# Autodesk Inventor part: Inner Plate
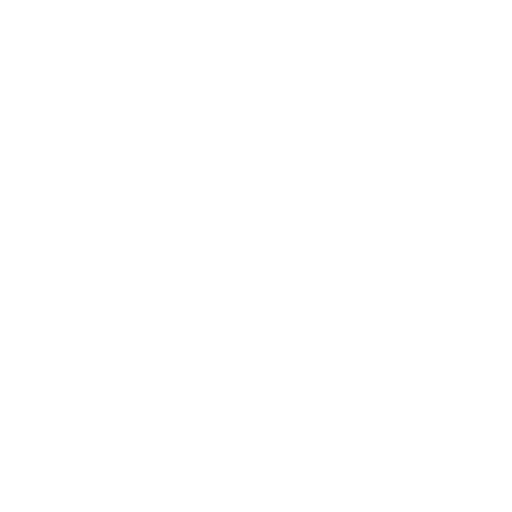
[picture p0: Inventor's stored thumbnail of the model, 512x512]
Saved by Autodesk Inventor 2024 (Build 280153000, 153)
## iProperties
Created: 2019-07
Part Number: Inner Plate
Material: Generic
Document SubType Name: Modeling
Designer: LENOVO-CADCIM
Density: 1 g/cm^3
Appearance: Default
Author: LENOVO-CADCIM
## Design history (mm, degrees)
